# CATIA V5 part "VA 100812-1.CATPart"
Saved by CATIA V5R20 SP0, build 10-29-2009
Part number: VA 100812-1
Revision: ANY
Definition: UNKNOWN
Nomenclature: VA 100812-1
Source: Unknown
Bounding box of the stored display mesh (mm): x -3.804 to 3.804, y 0 to 10.2, z -4 to 4
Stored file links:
  C:\Users\Utente\Desktop\IO LAVORO\3D X SITO CF\CUMSA\3D files VA\VA 100812\VA 100812-1.CATPart
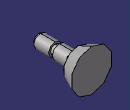
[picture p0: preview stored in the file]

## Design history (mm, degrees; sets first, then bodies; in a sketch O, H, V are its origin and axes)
Body1 "Chaflán1" (main body)
  Solid1: solid without history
